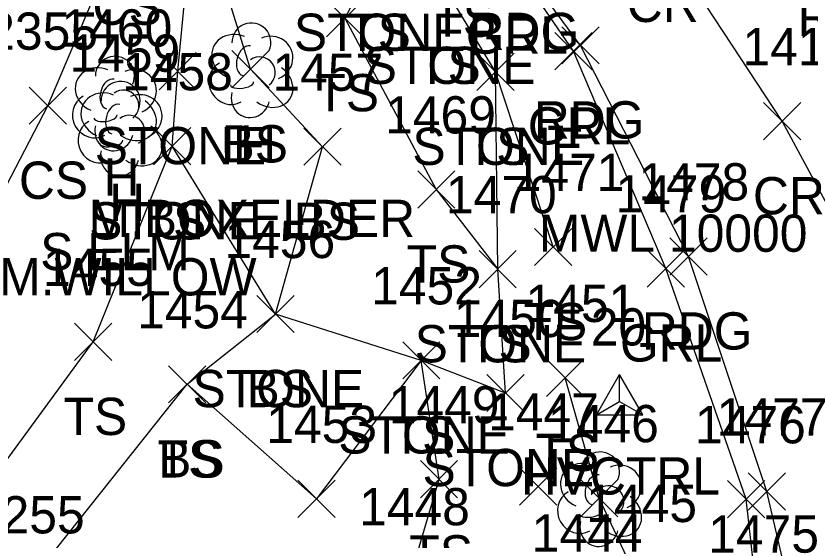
# Model space of a CAD drawing. Extents: x 1459992 to 1461532, y 647785 to 648535.
# Drawn here: x 1461331.07 to 1461373.72, y 648118.17 to 648146.3 of the extents above; entities that cross this region are included whole.
import ezdxf

# ---------------------------------------------------------------- set-up
doc = ezdxf.new("R2010")
doc.units = 0
for name, color, linetype in [('C_A', 7, 'Continuous'), ('C_I', 7, 'Continuous'), ('CPSM', 7, 'Continuous'), ('L_A', 7, 'Continuous'), ('L_C', 7, 'Continuous'), ('L_I', 7, 'Continuous'), ('L_TIC', 7, 'Continuous'), ('LASF', 7, 'Continuous'), ('LELB', 7, 'Continuous'), ('LTD', 7, 'Continuous'), ('P_A', 7, 'Continuous'), ('P_I', 7, 'Continuous'), ('P_TIC', 7, 'Continuous'), ('PEU', 7, 'Continuous'), ('PRC', 7, 'Continuous'), ('R_A', 7, 'Continuous'), ('R_I', 7, 'Continuous'), ('R_TIC', 7, 'Continuous'), ('RGR', 7, 'Continuous'), ('S_C', 7, 'Continuous')]:
    doc.layers.add(name, color=color, linetype=linetype)

msp = doc.modelspace()

# ---------------------------------------------------------------- linework, layer by layer
at = {"layer": 'CPSM'}
for p, q in [((1461362.24, 648124.891), (1461363.49, 648127.056)), ((1461364.74, 648124.891), (1461363.49, 648127.056)), ((1461363.491, 648125.612), (1461363.49, 648127.056)), ((1461362.24, 648124.891), (1461363.491, 648125.612)), ((1461363.491, 648125.612), (1461363.491, 648125.612)), ((1461363.491, 648125.612), (1461364.74, 648124.891)), ((1461362.24, 648124.891), (1461364.74, 648124.891))]:
    msp.add_line(p, q, dxfattribs=at)
at = {"layer": 'L_TIC'}
for points in [[(1461347.743, 648145.179), (1461349.743, 648147.179)], [(1461349.743, 648145.179), (1461347.743, 648147.179)], [(1461338.761, 648142.336), (1461340.761, 648144.336)], [(1461340.761, 648142.336), (1461338.761, 648144.336)], [(1461342.673, 648142.434), (1461344.673, 648144.434)], [(1461344.673, 648142.434), (1461342.673, 648144.434)], [(1461355.821, 648142.3), (1461357.821, 648144.3)], [(1461357.821, 648142.3), (1461355.821, 648144.3)], [(1461355.821, 648142.3), (1461357.821, 648144.3)], [(1461357.821, 648142.3), (1461355.821, 648144.3)], [(1461331.795, 648140.481), (1461333.795, 648142.481)], [(1461333.795, 648140.481), (1461331.795, 648142.481)], [(1461338.468, 648138.304), (1461340.468, 648140.304)], [(1461340.468, 648138.304), (1461338.468, 648140.304)], [(1461338.468, 648138.304), (1461340.468, 648140.304)], [(1461340.468, 648138.304), (1461338.468, 648140.304)], [(1461346.542, 648138.28), (1461348.542, 648140.28)], [(1461348.542, 648138.28), (1461346.542, 648140.28)], [(1461352.647, 648135.989), (1461354.647, 648137.989)], [(1461354.647, 648135.989), (1461352.647, 648137.989)], [(1461358.922, 648132.899), (1461360.922, 648134.899)], [(1461360.922, 648132.899), (1461358.922, 648134.899)], [(1461355.942, 648131.707), (1461357.942, 648133.707)], [(1461357.942, 648131.707), (1461355.942, 648133.707)], [(1461355.942, 648131.707), (1461357.942, 648133.707)], [(1461357.942, 648131.707), (1461355.942, 648133.707)], [(1461344.016, 648129.302), (1461346.016, 648131.302)], [(1461346.016, 648129.302), (1461344.016, 648131.302)], [(1461344.016, 648129.302), (1461346.016, 648131.302)], [(1461346.016, 648129.302), (1461344.016, 648131.302)], [(1461334.223, 648127.809), (1461336.223, 648129.809)], [(1461336.223, 648127.809), (1461334.223, 648129.809)], [(1461351.841, 648126.816), (1461353.841, 648128.816)], [(1461353.841, 648126.816), (1461351.841, 648128.816)], [(1461351.841, 648126.816), (1461353.841, 648128.816)], [(1461353.841, 648126.816), (1461351.841, 648128.816)], [(1461359.563, 648125.873), (1461361.563, 648127.873)], [(1461361.563, 648125.873), (1461359.563, 648127.873)], [(1461339.274, 648125.529), (1461341.274, 648127.529)], [(1461341.274, 648125.529), (1461339.274, 648127.529)], [(1461339.274, 648125.529), (1461341.274, 648127.529)], [(1461341.274, 648125.529), (1461339.274, 648127.529)], [(1461356.363, 648125.063), (1461358.363, 648127.063)], [(1461358.363, 648125.063), (1461356.363, 648127.063)], [(1461356.363, 648125.063), (1461358.363, 648127.063)], [(1461358.363, 648125.063), (1461356.363, 648127.063)], [(1461352.792, 648120.433), (1461354.792, 648122.433)], [(1461354.792, 648120.433), (1461352.792, 648122.433)], [(1461358.12, 648120.053), (1461360.12, 648122.053)], [(1461360.12, 648120.053), (1461358.12, 648122.053)], [(1461346.209, 648119.383), (1461348.209, 648121.383)], [(1461348.209, 648119.383), (1461346.209, 648121.383)], [(1461361.394, 648119.42), (1461363.394, 648121.42)], [(1461363.394, 648119.42), (1461361.394, 648121.42)]]:
    msp.add_lwpolyline(points, dxfattribs=at)
at = {"layer": 'LASF'}
for points in [[(1461357.363, 648126.063), (1461352.841, 648127.816), (1461345.016, 648130.302), (1461339.468, 648139.304), (1461339.761, 648143.336), (1461340.693, 648153.022), (1461343.313, 648158.745), (1461346.652, 648153.959), (1461348.313, 648152.755), (1461350.456, 648149.42), (1461354.207, 648147.646)], [(1461357.363, 648126.063), (1461356.942, 648132.707), (1461356.821, 648143.3), (1461354.207, 648147.646)]]:
    msp.add_lwpolyline(points, dxfattribs=at)
at = {"layer": 'LELB'}
for points in [[(1461254.788, 648024.689), (1461270.014, 648044.048), (1461286.662, 648058.61), (1461302.708, 648076.47), (1461318.859, 648092.871), (1461331.511, 648115.53), (1461340.274, 648126.529), (1461345.016, 648130.302), (1461347.542, 648139.28), (1461343.673, 648143.434), (1461340.693, 648153.022)], [(1461359.922, 648133.899), (1461356.821, 648143.3), (1461354.207, 648147.646), (1461355.023, 648150.176), (1461354.985, 648152.39)], [(1461222.105, 648019.642), (1461239.41, 648035.454), (1461252.966, 648048.327), (1461269.635, 648062.753), (1461277.559, 648070.159), (1461291.696, 648084.237), (1461310.278, 648105.504), (1461323.636, 648123.883), (1461332.795, 648141.481), (1461336.745, 648150.816)], [(1461350.456, 648149.42), (1461348.743, 648146.179), (1461353.647, 648136.989), (1461356.942, 648132.707)], [(1461226.023, 648017.252), (1461244.712, 648034.329), (1461263.294, 648051.101), (1461279.296, 648066.077), (1461297.191, 648082.439), (1461309.728, 648099.716), (1461327.419, 648118.176), (1461335.223, 648128.809), (1461339.468, 648139.304)], [(1461244.522, 647997.797), (1461264.749, 648013.285), (1461278.143, 648036.95), (1461298.413, 648049.424), (1461313.118, 648068.258), (1461328.135, 648085.894), (1461340.87, 648106.284), (1461352.192, 648115.964), (1461353.792, 648121.433), (1461352.841, 648127.816), (1461347.209, 648120.383), (1461340.274, 648126.529)], [(1461376.265, 648066.249), (1461375.178, 648079.9), (1461369.859, 648098.73), (1461365.162, 648108.989), (1461364.389, 648116.139), (1461362.394, 648120.42), (1461360.563, 648126.873)]]:
    msp.add_lwpolyline(points, dxfattribs=at)
at = {"layer": 'LTD'}
for p, q in [((1461343.673, 648143.434), (1461343.673, 648143.434)), ((1461343.673, 648143.434), (1461343.673, 648143.434)), ((1461336.347, 648141.65), (1461336.347, 648141.65)), ((1461336.347, 648141.65), (1461336.347, 648141.65)), ((1461336.65, 648140.3), (1461336.65, 648140.3)), ((1461336.65, 648140.3), (1461336.65, 648140.3)), ((1461362.394, 648120.42), (1461362.394, 648120.42)), ((1461362.394, 648120.42), (1461362.394, 648120.42))]:
    msp.add_line(p, q, dxfattribs=at)
for centre in [(1461343.72, 648144.868), (1461336.394, 648143.084), (1461336.697, 648141.734), (1461362.441, 648121.854)]:
    msp.add_arc(centre, 1.047, 335.5272, 180.9563, dxfattribs=at)
for centre, major_axis, ratio, start_param, end_param in [((1461342.881, 648144.101), (1.21, -0.512), 0.895232, 1.570796, 4.712389), ((1461344.715, 648144.018), (-1.141, -0.483), 0.949671, 1.570796, 4.712389), ((1461343.465, 648143.892), (-0.208, -0.792), 0.645439, 3.141593, 6.283185), ((1461344.173, 648143.268), (-0.5, 0.667), 0.989748, 3.141593, 6.283185), ((1461342.59, 648142.726), (0.584, -1.042), 0.959034, 3.141593, 6.283185), ((1461335.555, 648142.316), (1.21, -0.512), 0.895232, 1.570796, 4.712389), ((1461337.388, 648142.233), (-1.141, -0.483), 0.949671, 1.570796, 4.712389), ((1461344.673, 648142.601), (-1.09, 0.792), 0.841452, 1.570796, 4.712389), ((1461336.139, 648142.108), (-0.208, -0.792), 0.645439, 3.141593, 6.283185), ((1461343.215, 648142.684), (-0.625, -0.083), 0.423636, 0, 3.141593), ((1461335.859, 648140.966), (1.21, -0.512), 0.895232, 1.570796, 4.712389), ((1461336.847, 648141.483), (-0.5, 0.667), 0.989748, 3.141593, 6.283185), ((1461337.692, 648140.883), (-1.141, -0.483), 0.949671, 1.570796, 4.712389), ((1461343.673, 648141.934), (0.265, 1.061), 0.942809, 1.570796, 4.712389), ((1461335.264, 648140.941), (0.584, -1.042), 0.959034, 3.141593, 6.283185), ((1461336.442, 648140.758), (-0.208, -0.792), 0.645439, 3.141593, 6.283185), ((1461337.347, 648140.817), (-1.09, 0.792), 0.841452, 1.570796, 4.712389), ((1461335.889, 648140.9), (-0.625, -0.083), 0.423636, 0, 3.141593), ((1461337.151, 648140.133), (-0.5, 0.667), 0.989748, 3.141593, 6.283185), ((1461335.567, 648139.591), (0.584, -1.042), 0.959034, 3.141593, 6.283185), ((1461336.347, 648140.15), (0.265, 1.061), 0.942809, 1.570796, 4.712389), ((1461337.651, 648139.467), (-1.09, 0.792), 0.841452, 1.570796, 4.712389), ((1461336.192, 648139.55), (-0.625, -0.083), 0.423636, 0, 3.141593), ((1461336.651, 648138.8), (0.265, 1.061), 0.942809, 1.570796, 4.712389), ((1461361.602, 648121.087), (1.21, -0.512), 0.895232, 1.570796, 4.712389), ((1461363.435, 648121.003), (-1.141, -0.483), 0.949671, 1.570796, 4.712389), ((1461362.185, 648120.878), (-0.208, -0.792), 0.645439, 3.141593, 6.283185), ((1461362.894, 648120.253), (-0.5, 0.667), 0.989748, 3.141593, 6.283185), ((1461361.311, 648119.711), (0.584, -1.042), 0.959034, 3.141593, 6.283185), ((1461363.394, 648119.587), (-1.09, 0.792), 0.841452, 1.570796, 4.712389), ((1461361.936, 648119.67), (-0.625, -0.083), 0.423636, 0, 3.141593), ((1461362.394, 648118.92), (0.265, 1.061), 0.942809, 1.570796, 4.712389)]:
    msp.add_ellipse(centre, major_axis=major_axis, ratio=ratio, start_param=start_param, end_param=end_param, dxfattribs=at)
at = {"layer": 'P_TIC'}
for points in [[(1461360.392, 648143.718), (1461362.392, 648145.718)], [(1461362.392, 648143.718), (1461360.392, 648145.718)], [(1461371.213, 648139.65), (1461373.213, 648141.65)], [(1461373.213, 648139.65), (1461371.213, 648141.65)], [(1461366.19, 648132.394), (1461368.19, 648134.394)], [(1461368.19, 648132.394), (1461366.19, 648134.394)], [(1461370.389, 648119.78), (1461372.389, 648121.78)], [(1461372.389, 648119.78), (1461370.389, 648121.78)]]:
    msp.add_lwpolyline(points, dxfattribs=at)
at = {"layer": 'PEU'}
msp.add_lwpolyline([(1461390.506, 647801.302), (1461390.529, 647837.718), (1461390.801, 647875.02), (1461390.064, 647897.408), (1461389.914, 647928.517), (1461386.454, 647961.517), (1461383.38, 647992.893), (1461381.214, 648023.996), (1461378.9, 648057.005), (1461379.853, 648065.172), (1461378.22, 648080.013), (1461375.843, 648101.639), (1461371.389, 648120.78), (1461367.19, 648133.394), (1461361.392, 648144.718), (1461357.891, 648149.467), (1461353.744, 648153.756)], dxfattribs=at)
at = {"layer": 'PRC'}
msp.add_lwpolyline([(1461399.102, 647801.607), (1461400.203, 647838.194), (1461399.73, 647875.765), (1461399.539, 647898.401), (1461398.446, 647928.211), (1461395.012, 647961.974), (1461394.123, 647993.813), (1461392.15, 648024.041), (1461390.381, 648057.367), (1461388.518, 648080.662), (1461387.016, 648100.033), (1461383.866, 648115.79), (1461378.351, 648129.267), (1461372.213, 648140.65), (1461365.441, 648150.969), (1461358.126, 648158.61)], dxfattribs=at)
at = {"layer": 'R_TIC'}
for points in [[(1461360.016, 648143.4), (1461362.016, 648145.4)], [(1461362.016, 648143.4), (1461360.016, 648145.4)], [(1461364.964, 648131.75), (1461366.964, 648133.75)], [(1461366.964, 648131.75), (1461364.964, 648133.75)], [(1461369.285, 648119.361), (1461371.285, 648121.361)], [(1461371.285, 648119.361), (1461369.285, 648121.361)]]:
    msp.add_lwpolyline(points, dxfattribs=at)
at = {"layer": 'RGR'}
msp.add_lwpolyline([(1461368.238, 648109.163), (1461370.939, 648114.496), (1461370.285, 648120.361), (1461365.964, 648132.75), (1461361.016, 648144.4), (1461357.68, 648149.267), (1461354.985, 648152.39), (1461353.744, 648153.756)], dxfattribs=at)

# ---------------------------------------------------------------- texts
at = {"layer": 'C_A'}
msp.add_text('HVCTRL', height=2, dxfattribs=at).set_placement((1461358.184, 648120.612))
at = {"layer": 'C_I'}
msp.add_text('20', height=2, dxfattribs=at).set_placement((1461361.94, 648128.612))
at = {"layer": 'L_A'}
for s, p in [('CS', (1461335.186, 648145.816)), ('TS', (1461353.433, 648145.176)), ('STONE', (1461345.999, 648144.42)), ('TS', (1461348.865, 648144.42)), ('STONE', (1461349.75, 648142.646)), ('STONE', (1461349.75, 648142.646)), ('TS', (1461352.616, 648142.646)), ('TS', (1461347.153, 648141.179)), ('STONE', (1461335.305, 648138.336)), ('BS', (1461342.114, 648138.434)), ('H', (1461343.106, 648138.434)), ('STONE', (1461352.364, 648138.3)), ('TS', (1461355.23, 648138.3)), ('H', (1461335.78, 648136.65)), ('CS', (1461331.236, 648136.481)), ('H', (1461336.084, 648135.3)), ('STONE', (1461335.011, 648134.304)), ('TS', (1461337.877, 648134.304)), ('BS', (1461345.983, 648134.28)), ('TS', (1461352.057, 648131.989)), ('TS', (1461358.332, 648128.899)), ('STONE', (1461352.485, 648127.707)), ('TS', (1461355.351, 648127.707)), ('STONE', (1461340.559, 648125.302)), ('BS', (1461343.457, 648125.302)), ('TS', (1461333.633, 648123.809)), ('STONE', (1461348.384, 648122.816)), ('TS', (1461351.25, 648122.816)), ('TS', (1461358.972, 648121.873)), ('TS', (1461338.684, 648121.529)), ('BS', (1461338.715, 648121.529)), ('STONE', (1461352.906, 648121.063)), ('STONE', (1461352.906, 648121.063)), ('TS', (1461352.201, 648116.433))]:
    msp.add_text(s, height=2, dxfattribs=at).set_placement(p)
at = {"layer": 'L_C'}
for s, p in [('M.BOXELDER', (1461334.972, 648134.434)), ('S.ELM', (1461332.378, 648132.65)), ('M.WILLOW', (1461330.178, 648131.3))]:
    msp.add_text(s, height=2, dxfattribs=at).set_placement(p)
at = {"layer": 'L_I'}
for s, p in [('2355', (1461329.535, 648144.481)), ('1460', (1461333.52, 648144.65)), ('1459', (1461333.95, 648143.3)), ('1458', (1461336.775, 648142.304)), ('1458', (1461336.775, 648142.304)), ('1457', (1461344.849, 648142.28)), ('1469', (1461350.899, 648139.989)), ('1471', (1461357.796, 648136.899)), ('1470', (1461354.162, 648135.707)), ('1470', (1461354.162, 648135.707)), ('1456', (1461342.268, 648133.302)), ('1456', (1461342.268, 648133.302)), ('1455', (1461332.53, 648131.809)), ('1452', (1461350.148, 648130.816)), ('1452', (1461350.148, 648130.816)), ('1451', (1461358.437, 648129.873)), ('1454', (1461337.581, 648129.529)), ('1454', (1461337.581, 648129.529)), ('1450', (1461354.583, 648129.063)), ('1450', (1461354.583, 648129.063)), ('1449', (1461351.091, 648124.433)), ('1447', (1461356.427, 648124.053)), ('1453', (1461344.516, 648123.383)), ('1446', (1461359.646, 648123.42)), ('1446', (1461359.646, 648123.42)), ('1448', (1461349.499, 648118.964)), ('1445', (1461361.696, 648119.139)), ('1255', (1461328.818, 648118.53)), ('1444', (1461358.767, 648117.554))]:
    msp.add_text(s, height=2, dxfattribs=at).set_placement(p)
at = {"layer": 'P_A'}
for s, p in [('CR', (1461363.874, 648145.969)), ('RDG', (1461373.05, 648145.224)), ('RDG', (1461355.379, 648144.467)), ('RDG', (1461358.88, 648139.718)), ('CR', (1461370.646, 648135.65)), ('RDG', (1461364.678, 648128.394))]:
    msp.add_text(s, height=2, dxfattribs=at).set_placement(p)
at = {"layer": 'P_I'}
for s, p in [('1414', (1461370.087, 648143.65)), ('1478', (1461364.497, 648136.394)), ('1477', (1461368.696, 648123.78))]:
    msp.add_text(s, height=2, dxfattribs=at).set_placement(p)
at = {"layer": 'R_A'}
for p in [(1461355.223, 648144.267), (1461358.56, 648139.4), (1461363.507, 648127.75)]:
    msp.add_text('GRL', height=2, dxfattribs=at).set_placement(p)
at = {"layer": 'R_I'}
for s, p in [('1479', (1461363.263, 648135.75)), ('1476', (1461367.537, 648123.361)), ('1475', (1461368.246, 648117.496))]:
    msp.add_text(s, height=2, dxfattribs=at).set_placement(p)
at = {"layer": 'S_C'}
msp.add_text('MWL 10000 LBS CLEARANCE 10\'6"', height=2, dxfattribs=at).set_placement((1461359.156, 648133.639))

doc.saveas('drawing.dxf')
